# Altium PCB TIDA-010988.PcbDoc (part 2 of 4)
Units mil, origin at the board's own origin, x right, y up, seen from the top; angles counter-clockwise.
Board outline 3937.01 x 2559.06 mil, 4 copper layers (Top Layer, GND1, GND2, Bottom Layer), stack 61.6 mil thick; 270 components, 141 nets, 796 pads, 474 vias.
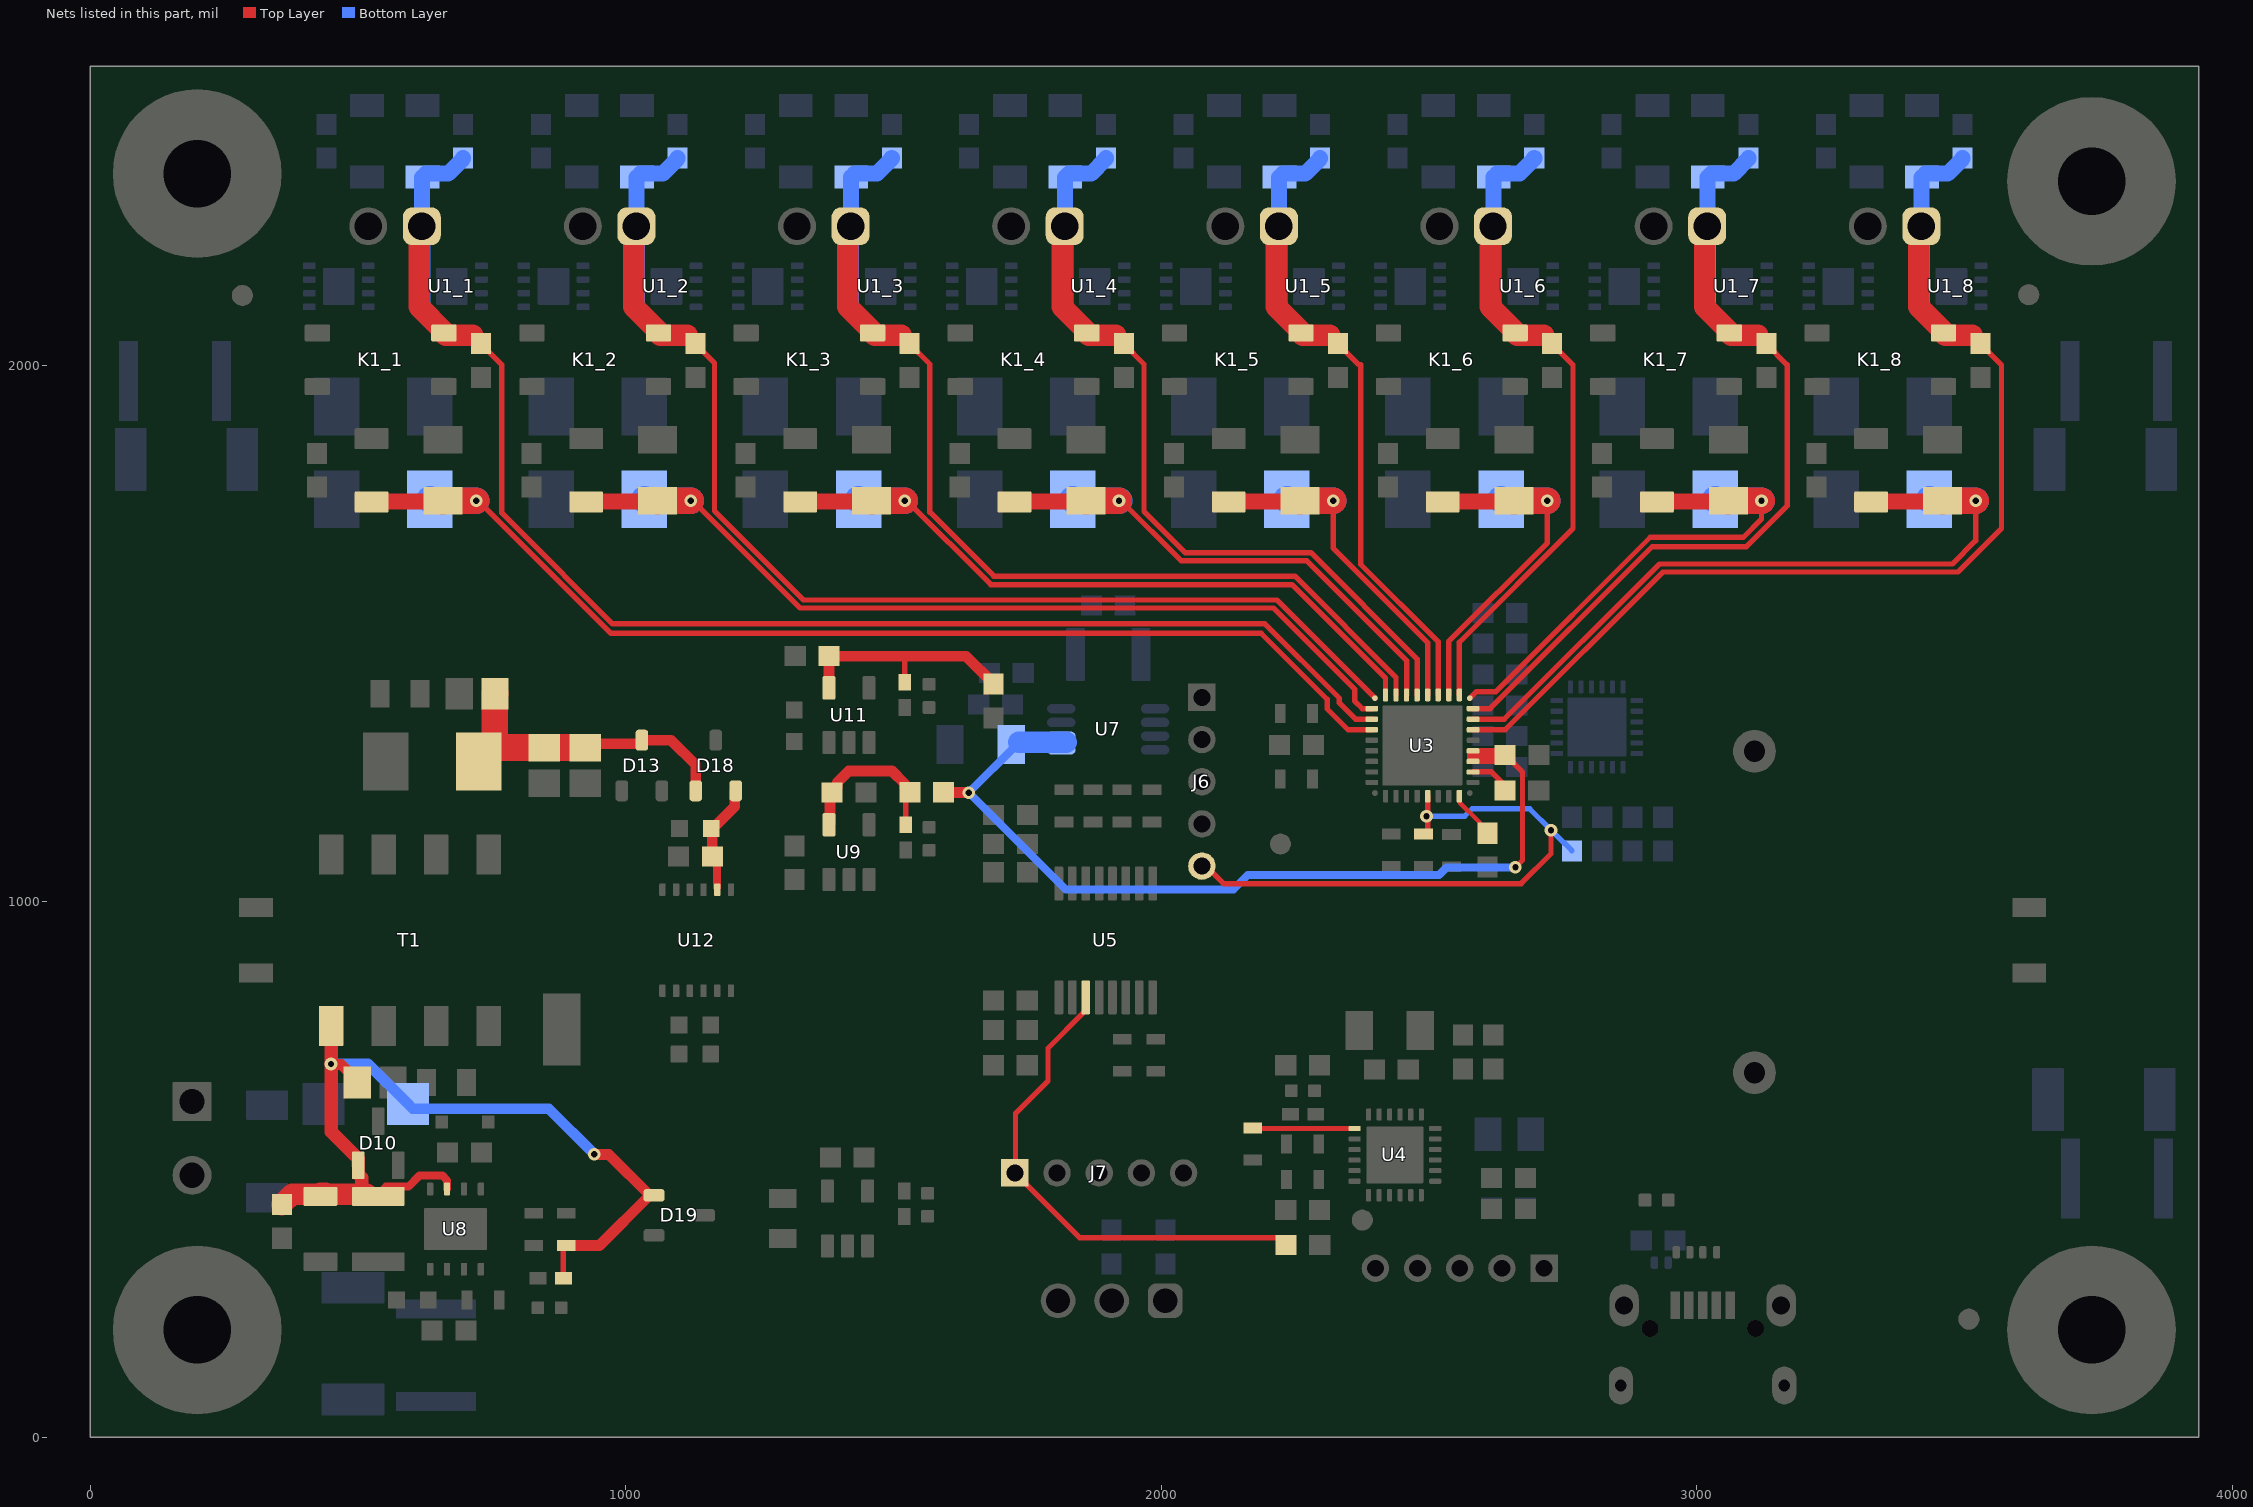
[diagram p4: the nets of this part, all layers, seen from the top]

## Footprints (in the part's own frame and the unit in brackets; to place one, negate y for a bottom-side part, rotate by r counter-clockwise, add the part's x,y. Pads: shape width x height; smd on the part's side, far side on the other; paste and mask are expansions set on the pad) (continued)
WCAP-CSGP_0603_L1.6W0.8H0.8_Reflow [mm] "Ceramic Capacitors, body 1.6x0.8mm"
  rect 0.8x0.8 smd: 1(-0.75,0) 2(0.75,0)
  body extent -0.8,-0.4 0.8,0.4, height 0.8
WCAP-CSGP_0805_L2W1.25H0.6_Reflow [mm] "Ceramic Capacitors, body 2x1.25mm"
  rect 0.9x1.3 smd: 1(-0.95,0) 2(0.95,0)
  body extent -1,-0.63 1,0.63, height 0.6
WCAP-CSGP_0805_L2W1.25H1.25 [mm] "Ceramic Capacitors, body 2x1.25mm"
  rect 0.9x1.3 smd: 1(-0.95,0) 2(0.95,0)
  body extent -1,-0.63 1,0.63, height 1.25
WCAP-CSMH_1206_L3.2W1.6H1.6 [mm] "Ceramic Capacitors, body 3.2x1.6mm"
  rect 0.9x1.6 smd: 1(-1.55,0) 2(1.55,0)
  silkscreen extent -0.75,-0.87 0.75,0.87, body extent -1.6,-0.8 1.6,0.8, height 1.6
WCAP-CSMH_1812_L4.5W3.2H2.5 [mm] "Ceramic Capacitors, body 4.5x3.2mm"
  rect 0.9x3.8 smd: 1(-2.2,0) 2(2.2,0)
  silkscreen extent -1.4,-1.75 1.4,1.75, body extent -2.25,-1.6 2.25,1.6, height 2.5
WEEE_Minimum [mil] "WEEElie bin"
  silkscreen extent -95,-172 99,104
WL-SMCC_0402_Green [mm] "SMD, 2-Leads, Body 1x0.5mm"
  rrect17% 0.6x0.6 smd: 1(-0.55,0) 2(0.55,0)
  body extent -0.5,-0.25 0.5,0.25, height 0.39
WURTH_61300311121 [mm] "Header, 2.54mm, 3x1, TH"
  rrect50% 1.65x1.65 hole 1.15: 1(-2.54,0)
  round 1.65 hole 1.15: 2(0,0) 3(2.54,0)
  body extent -3.81,-1.27 3.81,1.27, height 8.54
Wurth_691210910002 [mm] "Receptacle, 2.54mm, 2x1, R/A, TH"
  rrect50% 1.8x1.8 hole 1.3: 1(-1.27,0)
  round 1.8 hole 1.3: 2(1.27,0)
  silkscreen extent -3.2,-3.25 2.77,3.25, body extent -2.77,-3.25 2.77,3.25, height 8.85

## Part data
C1_1 C1_2 C1_3 C1_4 C1_5 C1_6 C1_7 C1_8 C2_1 C2_2 C2_3 C2_4 C2_5 C2_6 C2_7 C2_8: library part CMP-0084048-1, "CAP, CERM, 0.022 µF, 1000 V,+/- 10%, X7R, AEC-Q200 Grade 1, 1206", Cap_Case=1206, Manufacturer=Kemet, TempCo=X7R, Tolerance_%=10%, Value2=1000V, ValueDisplayed=0.022µF
C3 C4 C5 C6 C7 C8 C23: library part CMP-0006833-4, "CAP, CERM, 1 uF, 25 V, +/- 10%, X7R, 0603", Cap_Case=0603, Manufacturer="Wurth Elektronik", Supplier Part Number 1=732-7994-1-ND, TempCo=X7R, Tolerance_%=10%, Value1=Unknown, Value2=25V, ValueDisplayed=1uF
C9 C10 C11 C12 C13 C14 C16 C39: library part CMP-0006832-5, "CAP, CERM, 0.1 uF, 25 V, +/- 10%, X7R, 0603", Cap_Case=0603, Manufacturer="Wurth Elektronik", Supplier Part Number 1=710-885012206071, TempCo=X7R, Tolerance_%=10%, Value1=Unknown, Value2=25V, ValueDisplayed=0.1uF
C15: library part CMP-0006975-4, "CAP, CERM, 0.01 uF, 25 V, +/- 5%, C0G/NP0, 0603", Cap_Case=0603, Manufacturer=Kemet, Supplier Part Number 1=399-5779-1-ND, TempCo=C0G/NP0, Tolerance_%=5%, Value1=Unknown, Value2=25V, ValueDisplayed=0.01uF
C17 C22: library part CMP-0008574-2, "CAP, CERM, 10 uF, 25 V, +/- 10%, X7R, 1206", Cap_Case=1206, Manufacturer="Wurth Elektronik", Supplier Part Number 1=732-7574-1-ND, TempCo=X7R, Tolerance_%=10%, Value1=Unknown, Value2=25V, ValueDisplayed=10uF
C18: library part CMP-0119379-1, "WCAP-CSGP Multilayer Ceramic Chip Capacitor, General Purpose, size 0603, X7R, 470nF, 25VDC", Capacitance Tolerance=+/-10%, Case/Size Code=0603, Insulation Resistance=1.1GOhm, Manufacturer="Wurth Elektronik", Operating Temperature Max=125°C, Operating Temperature Min=-55°C, Rated Voltage (DC)=25V
C19: library part CMP-0007576-2, "CAP, CERM, 0.47 uF, 25 V, +/- 10%, X5R, 0805", Cap_Case=0805, Manufacturer=AVX, Supplier Part Number 1=478-1407-1-ND, TempCo=X5R, Tolerance_%=10%, Value1="0.017 ohm", Value2=25V, ValueDisplayed=0.47uF
C20 C30: library part CMP-0119825-1, "WCAP-CSMH Multilayer Ceramic Chip Capacitor, Mid and High Voltage, size 1206, X7R Class II, 1nF, 2000VDC", Capacitance Tolerance=10%, Case/Size Code=1206, Insulation Resistance=10GOhm, Manufacturer="Wurth Elektronik", Operating Temperature Max=125°C, Operating Temperature Min=-55°C, Rated Voltage (DC)=2000V
C21: library part CMP-0096740-1, "22 µF ±10% 25V Ceramic Capacitor X7R 1210 (3225 Metric)", Manufacturer=Wurth, Operating Temperature Range="-55°C to +125°C", TempCo=15%, Temperature Characteristic=X7R, Tolerance_%=10%, ValueDisplayed=22uF
C24 C25: library part CMP-0119848-1, "WCAP-CSMH Multilayer Ceramic Chip Capacitor, Mid and High Voltage, size 1812, X7R Class II, 2.2nF, 3000VDC", Capacitance Tolerance=10%, Case/Size Code=1812, Insulation Resistance=10GOhm, Manufacturer="Wurth Elektronik", Operating Temperature Max=125°C, Operating Temperature Min=-55°C, Rated Voltage (DC)=3000V
C26 C27: library part CMP-0118967-1, "WCAP-CSGP Multilayer Ceramic Chip Capacitor, General Purpose, size 0805, NP0, 22pF, 50VDC", Capacitance Tolerance=+/-5%, Case/Size Code=0805, Insulation Resistance=10GOhm, Manufacturer="Wurth Elektronik", Operating Temperature Max=125°C, Operating Temperature Min=-55°C, Rated Voltage (DC)=50V
C28 C29: library part CMP-0078699-1, "CAP, CERM, 47 µF, 10 V,+/- 20%, X5R, 0805", Cap_Case=0805, Manufacturer=MuRata, Supplier Part Number 1=490-9961-1-ND, TempCo=X5R, Tolerance_%=20%, Value2=10V, ValueDisplayed=47µF
C31: library part CMP-0088282-2, "4.7µF ±10% 50V Ceramic Capacitor X7R 1206 (3216 Metric)", Manufacturer="Wurth Electronics", TempCo=15%, Tolerance_%=10%, ValueDisplayed=4.7uF
C32: library part CMP-0096739-1, "4.7 µF ±10% 50V Ceramic Capacitor X7R 1210 (3225 Metric)", Digikey Part Number=732-7386-1-ND, Manufacturer=Wurth, Mouser Part Number=710-885012209048, Operating Temperature Range="-55°C to +125°C", TempCo=15%, Temperature Characteristic=X7R, Tolerance_%=10%, ValueDisplayed=4.7uF
C33: library part CMP-0006837-4, "CAP, CERM, 0.1 uF, 50 V, +/- 10%, X7R, 0603", Cap_Case=0603, Manufacturer="Wurth Elektronik", TempCo=X7R, Tolerance_%=10%, Value1=Unknown, Value2=50V, ValueDisplayed=0.1uF
C34: library part CMP-0119400-1, "WCAP-CSGP Multilayer Ceramic Chip Capacitor, General Purpose, size 0603, X7R, 47nF, 50VDC", Capacitance Tolerance=+/-10%, Case/Size Code=0603, Insulation Resistance=10GOhm, Manufacturer="Wurth Elektronik", Operating Temperature Max=125°C, Operating Temperature Min=-55°C, Rated Voltage (DC)=50V
C35 C36 C38 C40: library part CMP-0006831-4, "CAP, CERM, 1 uF, 16 V, +/- 10%, X7R, 0603", Cap_Case=0603, Manufacturer="Wurth Elektronik", Supplier Part Number 1=710-885012206052, TempCo=X7R, Tolerance_%=10%, Value1=Unknown, Value2=16V, ValueDisplayed=1uF
C37: library part CMP-0119543-1, "WCAP-CSGP Multilayer Ceramic Chip Capacitor, General Purpose, size 0805, X7R Class II, 470nF, 100VDC", Capacitance Tolerance=+/-10%, Case/Size Code=0805, Insulation Resistance=0.2GOhm, Manufacturer="Wurth Elektronik", Operating Temperature Max=125°C, Operating Temperature Min=-55°C, Rated Voltage (DC)=100V
C41 C43: library part CMP-0119369-1, "WCAP-CSGP Multilayer Ceramic Chip Capacitor, General Purpose, size 0603, X7R, 15nF, 25VDC", Capacitance Tolerance=+/-10%, Case/Size Code=0603, Insulation Resistance=10GOhm, Manufacturer="Wurth Elektronik", Operating Temperature Max=125°C, Operating Temperature Min=-55°C, Rated Voltage (DC)=25V
C42: library part CMP-0096736-1, "10 µF ±20% 25V Ceramic Capacitor X5R 0603 (1608 Metric)", Manufacturer=Wurth, Operating Temperature Range="-55°C to +85°C", TempCo=15%, Temperature Characteristic=X5R, Tolerance_%=20%, ValueDisplayed=10uF
C44: library part CMP-0081159-1, "CAP, CERM, 22 µF, 16 V,+/- 20%, X5R, 0603", Cap_Case=0603, Manufacturer=Samsung, Supplier Part Number 1=1276-7076-1-ND, TempCo=X5R, Tolerance_%=20%, Value2=16V, ValueDisplayed=22µF
C45 C46: library part CMP-0115919-1, "WCAP-CSMH Multilayer Ceramic Chip Capacitor, Mid and High Voltage, size 1812, X7R Class II, 2.2nF, 3000VDC", Capacitance Tolerance=10%, Case/Size Code=1812, Insulation Resistance=10GOhm, Manufacturer="Wurth Elektronik", Operating Temperature Max=125°C, Operating Temperature Min=-55°C, Rated Voltage (DC)=3000V
D1_1 D1_2 D1_3 D1_4 D1_5 D1_6 D1_7 D1_8 D2_1 D2_2 D2_3 D2_4 D2_5 D2_6 D2_7 D2_8: library part CMP-0005627-4, "Diode, Zener, 11 V, 550 mW, SMB", Manufacturer="ON Semiconductor", Power_W=550mW, Value1=0.55W
D3 D7 D15 D17 D20 D21: library part CMP-0081765-2, "LED, Green, SMD", Color=Green, Manufacturer="Wurth Elektronik", Power_TotalModule=99mW, Value1=0.099W, Value2=3.2V
D4 D5 D6: library part CMP-0074647-4, "1-Channel ESD Protection Diode with Low RDYN and Low Clamping Voltage, DPY0002A (X1SON-2)", Alternate Manufacturer="Texas Instruments", Alternate PartNumber=ESD401DPYT, Operating Temperature Range="-40 to 125 C", Rating=Catalog
D10: library part CMP-0126396-1, "Zener Diode 27 V 250 mW ±5% Surface Mount SOT-23-3", Digikey Part Number=296-BZX84C27VDBZRQ1CT-ND, Manufacturer="Texas Instruments", Max Reverse Leakage Current=0.03uA, Mouser Part Number=595-BZX84C27VDBZRQ1, Operating Temperature Range="-55°C to +150°C", Power_W=250mW
D11: library part CMP-0028909-2, "Diode, Schottky, 30 V, 2 A, AEC-Q101, SMB", Manufacturer=Vishay-Semiconductor, Value1=2A, Value2=0.47V
D12: library part CMP-0029019-2, "Diode, Ultrafast, 75 V, 0.25 A, SOD-323", Manufacturer="Central Semiconductor", Value1=0.25A, Value2=1.2V
D13: library part CMP-0005972-3, "Diode, Zener, 8.2 V, 225 mW, SOT-23", Manufacturer="ON Semiconductor", Power_W=225mW, Value1=0.225W
D14: library part CMP-0028353-2, "Diode, Schottky, 40 V, 3 A, SMA", Manufacturer="Diodes Inc.", Value1=3A, Value2=0.5V
D16: library part CMP-0088101-2, "DIODE SCHOTTKY 20V 1A PMDTM", Manufacturer=Rohm
D18 D19: library part CMP-0028570-2, "Diode, Schottky, 20 V, 0.4 A, SOT-23", Manufacturer="Diodes Inc.", Value1=0.4A, Value2=0.35V
F1_1 F1_2 F1_3 F1_4 F1_5 F1_6 F1_7 F1_8: library part CMP-0125283-2, "Polymeric PTC Resettable Fuse 30V 200 mA Ih Surface Mount 1206 (3216 Metric), Concave", Digikey Part Number=18-NANOASMDCH020F-2CT-ND, Hold Current=0.2A, Manufacturer=Littelfuse, Mouser Part Number=576-NANOASMDCH020F-2, Operating Temperature Range="-40°C to +125°C", Trip Current=0.6A
FID1 FID2 FID3 FID4 FID5 FID6: library part CMP-0077181-1, "Fiducial mark.  There is nothing to buy or mount.", Manufacturer=N/A
H1 H2 H3 H4: library part CMP-0003617-1, "Machine Screw, Round, #4-40 x 1/4, Nylon, Philips panhead", Manufacturer="B&F Fastener Supply", Supplier Part Number 1=H542-ND
H5 H6 H7 H8: library part CMP-0003610-1, "Standoff, Hex, 0.5\"L #4-40 Nylon", Manufacturer=Keystone, Supplier Part Number 1=36-1902C-ND
J1_1 J1_2 J1_3 J1_4 J1_5 J1_6 J1_7 J1_8: library part CMP-0054769-2, "Receptacle, 2.54mm, 2x1, Tin, R/A, TH", Color=Green, Current_A=6A, Manufacturer="Wurth Elektronik", Voltage_V=150V
J2: library part CMP-0086695-3, "USB - micro B USB 2.0 Receptacle Connector 5 Position Surface Mount, Right Angle; Through Hole", Current_A=3A, Manufacturer="Wurth Electronics", Voltage_V=30V
J3: library part CMP-0054796-4, "Header, 2.54 mm, 3x1, Gold, TH", Manufacturer="Wurth Elektronik", Supplier Part Number 1=732-5316-ND
J4 J6 J7: library part CMP-0075212-1, "Header, 2mm, 5x1, Gold, TH", Color=Black, Current_A=1A, Manufacturer=Harwin, Supplier Part Number 1=952-1314-ND, Voltage_V=500V
J5: library part CMP-0095471-2, "2 Position Wire to Board Terminal Block Horizontal with Board 0.138\" (3.50mm) Through Hole", Current_A=10A, Digikey Part Number=732-2745-ND, Manufacturer=Wurth, Mouser Part Number=710-691103110002, Operating Temperature Range="-40°C to +105°C", Voltage_V=125V
K1_1 K1_2 K1_3 K1_4 K1_5 K1_6 K1_7 K1_8: library part CMP-0125248-1, "Relay SSR 1mA 1.75V DC-IN 2A 60V AC/DC-OUT 4-Pin SOP Tube", Digikey Part Number=255-AQY232G3HS-ND, Input Current=20mA, Manufacturer=Panasonic, Max Power Dissipation=530mW, Mouser Part Number=769-AQY232G3HS, On State Resistance=0.07Ω, Operating Temperature Range="-40°C to +125°C", Output Voltage=48V, ValueDisplayed=0.8pF, Voltage_Isolation_Vrms=3750Vrms
L1 L2 L3 L4 L5: library part CMP-0003285-2, "Ferrite Bead, 600 ohm @ 100 MHz, 1 A, 0603", Manufacturer="Wurth Elektronik", Supplier Part Number 1=732-6703-1-ND, Value1="0.2 ohm", Value2=1A, ValueDisplayed="600 ohm"
LBL1: library part CMP-0003625-1, "Thermal Transfer Printable Labels, 0.650\" W x 0.200\" H - 10,000 per roll", Manufacturer=Brady, Supplier Part Number 1=97C5133
Logo1: library part CMP-0074844-2, Manufacturer="Texas Instruments"
Logo2: library part CMP-0074838-1, "Texas Instrument Corporate Signature"
Logo3: library part CMP-0074847-1, "FCC_disclaimer"
Logo4: library part CMP-0074769-4, Manufacturer="Texas Instruments"
R0_1 R0_2 R0_3 R0_4 R0_5 R0_6 R0_7 R0_8 R6 R15 R23 R26: library part CMP-0025697-4, "RES, 0, 5%, 0.1 W, AEC-Q200 Grade 0, 0603", Manufacturer=Vishay-Dale, Power_W=100mW, Supplier Part Number 1=541-0.0GCT-ND, TempCo="200 ppm/C", Tolerance_%=5%, Value2=0.1W, Value_Code=0000, ValueDisplayed=0
R1_1 R1_2 R1_3 R1_4 R1_5 R1_6 R1_7 R1_8 R2_1 R2_2 R2_3 R2_4 R2_5 R2_6 R2_7 R2_8: library part CMP-0023358-4, "RES, 10 M, 0.5%, 0.1 W, AEC-Q200 Grade 0, 0603", Manufacturer=Vishay-Dale, Power_W=100mW, Supplier Part Number 1=541-10MAYCT-ND, TempCo="50 ppm/C", Tolerance_%=0.5%, Value2=0.1W, Value_Code=10M0, ValueDisplayed=10M
R3_1 R3_2 R3_3 R3_4 R3_5 R3_6 R3_7 R3_8: library part CMP-0024131-2, "RES, 340, 0.1%, 0.1 W, 0603", Manufacturer="Yageo America", Power_W=100mW, TempCo="25 ppm/C", Tolerance_%=0.1%, Value2=0.1W, Value_Code=340R, ValueDisplayed=340
R4_1 R4_2 R4_3 R4_4 R4_5 R4_6 R4_7 R4_8: library part CMP-0018822-2, "RES, 249, 0.1%, 0.25 W, 1206", Manufacturer=Vishay-Dale, Power_W=250mW, Supplier Part Number 1=TNP249ACCT-ND, TempCo="25 ppm/C", Tolerance_%=0.1%, Value2=0.25W, Value_Code=249R, ValueDisplayed=249
R5 R9 R12 R17 R18 R19 R20 R21 R22 R29 R30: library part CMP-0025334-3, "RES, 49.9, 0.5%, 0.1 W, 0603", Manufacturer="Yageo America", Power_W=100mW, TempCo="50 ppm/C", Tolerance_%=0.5%, Value2=0.1W, Value_Code=49R9, ValueDisplayed=49.9
R7: library part CMP-0025862-4, "RES, 8.2 k, 5%, 0.1 W, AEC-Q200 Grade 0, 0603", Manufacturer=Vishay-Dale, Power_W=100mW, Supplier Part Number 1=541-8.2KGCT-ND, TempCo="200 ppm/C", Tolerance_%=5%, Value2=0.1W, Value_Code=8k20, ValueDisplayed=8.2k
R8: library part CMP-0023032-4, "RES, 330 k, 1%, 0.1 W, 0603", Manufacturer=Yageo, Power_W=100mW, Supplier Part Number 1=311-330KHRCT-ND, TempCo="100 ppm/C", Tolerance_%=1%, Value2=0.1W, Value_Code=330k
R10 R56: library part CMP-0021998-4, "RES, 10.0 k, 1%, 0.1 W, AEC-Q200 Grade 0, 0603", Manufacturer=Vishay-Dale, Power_W=100mW, Supplier Part Number 1=541-10.0KHCT-ND, TempCo="100 ppm/C", Tolerance_%=1%, Value2=0.1W, Value_Code=10k0, ValueDisplayed=10.0k
R11: library part CMP-0022917-4, "RES, 220 k, 1%, 0.1 W, 0603", Manufacturer=Yageo, Power_W=100mW, Supplier Part Number 1=311-220KHRCT-ND, TempCo="100 ppm/C", Tolerance_%=1%, Value2=0.1W, Value_Code=220k
R13 R14 R27 R28 R31 R32: library part CMP-0023153-5, "RES, 4.70 k, 1%, 0.1 W, 0603", Manufacturer=Yageo, Power_W=100mW, Supplier Part Number 1=311-4.70KHRCT-ND, TempCo="100 ppm/C", Tolerance_%=1%, Value2=0.1W, Value_Code=4k70, ValueDisplayed=4.70k
R16 R25: library part CMP-0025925-5, "RES, 47 k, 5%, 0.1 W, 0603", Manufacturer=Yageo, Power_W=100mW, Supplier Part Number 1=311-47KGRCT-ND, TempCo="100 ppm/C", Tolerance_%=5%, Value2=0.1W, Value_Code=47k0, ValueDisplayed=47k
R24: library part CMP-0023363-3, "RES, 100 k, 0.1%, 0.1 W, AEC-Q200 Grade 0, 0603", Manufacturer=Panasonic, Power_W=100mW, Supplier Part Number 1=P100KDBCT-ND, TempCo="25 ppm/C", Tolerance_%=0.1%, Value2=0.1W, Value_Code=100k
R33: library part CMP-0023427-3, "RES, 120 k, 0.1%, 0.1 W, 0603", Manufacturer="Susumu Co Ltd", Power_W=100mW, Supplier Part Number 1=RG16P120KBCT-ND, TempCo="25 ppm/C", Tolerance_%=0.1%, Value2=0.1W, Value_Code=120k
R34 R54 R55: library part CMP-0026918-5, "RES, 3.3 k, 5%, 0.063 W, AEC-Q200 Grade 0, 0402", Manufacturer=Vishay-Dale, Power_W=63mW, Supplier Part Number 1=541-3.3KJCT-ND, TempCo="200 ppm/C", Tolerance_%=5%, Value2=0.063W, Value_Code=3k30, ValueDisplayed=3.3k
R35: library part CMP-0022726-3, "RES, 0.047, 1%, 0.1 W, AEC-Q200 Grade 1, 0603", Manufacturer=Panasonic, Power_W=100mW, Supplier Part Number 1=P47LJCT-ND, TempCo="200 ppm/C", Tolerance_%=1%, Value2=0.1W, Value_Code=R047, ValueDisplayed=0.047
R36 R37 R39 R40: library part CMP-0089022-1, "RES SMD 3.3M OHM 1% 1/2W 2010", Manufacturer=Bourns, Power_W=500mW, TempCo=100ppm/°C, Tolerance_%=1%
R41: library part CMP-0026982-5, "RES, 8.2 k, 5%, 0.063 W, AEC-Q200 Grade 0, 0402", Manufacturer=Vishay-Dale, Power_W=63mW, Supplier Part Number 1=541-8.2KJCT-ND, TempCo="200 ppm/C", Tolerance_%=5%, Value2=0.063W, Value_Code=8k20, ValueDisplayed=8.2k
R42 R43: library part CMP-0018851-2, "RES, 100, 0.1%, 0.125 W, 0805", Manufacturer="Susumu Co Ltd", Power_W=125mW, Supplier Part Number 1=RG20P100BCT-ND, TempCo="25 ppm/C", Tolerance_%=0.1%, Value2=0.125W, Value_Code=100R, ValueDisplayed=100
R46: library part CMP-0026963-3, "RES, 68 k, 5%, 0.063 W, AEC-Q200 Grade 0, 0402", Manufacturer=Vishay-Dale, Power_W=63mW, Supplier Part Number 1=541-68KJCT-ND, TempCo="200 ppm/C", Tolerance_%=5%, Value2=0.063W, Value_Code=68k0, ValueDisplayed=68k
R47: library part CMP-0023174-4, "RES, 536 k, 1%, 0.1 W, 0603", Manufacturer=Yageo, Power_W=100mW, Supplier Part Number 1=311-536KHRCT-ND, TempCo="100 ppm/C", Tolerance_%=1%, Value2=0.1W, Value_Code=536k
R48: library part CMP-0022836-4, "RES, 174 k, 1%, 0.1 W, 0603", Manufacturer=Yageo, Power_W=100mW, Supplier Part Number 1=311-174KHRCT-ND, TempCo="100 ppm/C", Tolerance_%=1%, Value2=0.1W, Value_Code=174k
R50: library part CMP-0022735-5, "RES, 100 k, 1%, 0.1 W, 0603", Manufacturer=Yageo, Power_W=100mW, Supplier Part Number 1=311-100KHRCT-ND, TempCo="100 ppm/C", Tolerance_%=1%, Value2=0.1W, Value_Code=100k
R51: library part CMP-0022784-4, "RES, 130 k, 1%, 0.1 W, 0603", Manufacturer=Yageo, Power_W=100mW, Supplier Part Number 1=311-130KHRCT-ND, TempCo="100 ppm/C", Tolerance_%=1%, Value2=0.1W, Value_Code=130k
R52: library part CMP-0022776-5, "RES, 12.1 k, 1%, 0.1 W, 0603", Manufacturer=Yageo, Power_W=100mW, Supplier Part Number 1=311-12.1KHRCT-ND, TempCo="100 ppm/C", Tolerance_%=1%, Value2=0.1W, Value_Code=12k1, ValueDisplayed=12.1k
T1: library part CMP-0096072-1, "Transformer, 0.13Ohm PRI, 0.019Ohm SEC, 3:1, 9.5x9.78x10.54mm SMT", Frequency_Fixed=350kHz, Manufacturer="Wurth Electronics", Operating Temperature Range="-40°C to +125°C"
TP1 TP2: library part CMP-0055138-2, "Test Point, Miniature, Black, TH", Color=Black, Manufacturer="Keystone Electronics", PartNumber=5001, Supplier Part Number 1=36-5001-ND
TP3 TP4: library part CMP-0003825-1, "1mm Test Point, SMT", Manufacturer=Any, PartNumber=TP_SM_1MM
TP5: library part CMP-0055152-2, "Test Point, Miniature, SMT", Manufacturer="Keystone Electronics", PartNumber=5015, Supplier Part Number 1=36-5015TR-ND
U1_1 U1_2 U1_3 U1_4 U1_5 U1_6 U1_7 U1_8 U2_1 U2_2 U2_3 U2_4 U2_5 U2_6 U2_7 U2_8: library part CMP-0081715-3, "33 V Bidirectional Flat-Clamp Surge Protection Device, DRB0008A (VSON-8)", Alternate Manufacturer="Texas Instruments", Alternate PartNumber=TVS3301DRBT, Operating Temperature Range="-40 to 125 C", Rating=Catalog
U3: library part CMP-0120762-1, Manufacturer="Texas Instruments", Operating Temperature Range=to
U4: library part CMP-0093957-1, "Mixed-Signal Microcontroller, VQFN24", Frequency_Fixed=80MHz, Manufacturer="Texas Instruments", Max Supply Voltage=3.6V, Min Supply Voltage=1.62V, Operating Temperature Range="-40°C to +125°C"
U5: library part CMP-0127533-1, "General-Purpose, Basic and Reinforced, Quad-Channel Digital Isolators", Alternate Manufacturer="Texas Instruments", Alternate PartNumber=ISO7741DBQ, PartNumber=ISO7741DBQR
U6: library part CMP-0122830-1, Manufacturer="Texas Instruments", Operating Temperature Range=to
U7: library part CMP-0076433-2, "5ppm/C High-Precision Voltage Reference with Integrated High-Bandwidth Buffer, DGK0008A (VSSOP-8)", Alternate Manufacturer="Texas Instruments", Alternate PartNumber=REF6025IDGKT
U8: library part CMP-0084791-1, "70-VIN PSR Flyback DC/DC Converter With 100-V, 1.5-A Integrated Power MOSFET, NGU0008C (WSON-8)", Alternate Manufacturer="Texas Instruments", Alternate PartNumber=LM5180NGUT
U9: library part CMP-0091339-1, "300-mA, ultra-low-noise, low-IQ, low-dropout (LDO) linear regulator with high PSRR 5-SOT-23 -40 to 125", Dropout Voltage=140mV, Manufacturer="Texas Instruments", Max Supply Voltage=6V, Min Supply Voltage=1.6V, Mouser Part Number=595-TPS7A2050PDBVR, Nominal Supply Current=6.5uA, Operating Temperature Range="-40°C to +125°C", Output Voltage=5V
U10 U11: library part CMP-0034271-1, "150-mA 30-V low-dropout (LDO) linear regulator with 3.2-μA supply current 5-SOT-23 -40 to 125", Digikey Part Number=296-TLV709A33DBVRCT-ND, Dropout Voltage=1000mV, Manufacturer="Texas Instruments", Max Supply Voltage=30V, Min Supply Voltage=4.3V, Mouser Part Number=595-TLV709A33DBVR, Nominal Supply Current=3.2uA, Operating Temperature Range="-40°C to +125°C", Output Voltage=3.3V
U12: library part CMP-0098322-4, "1.5W, High-Density, >3 kVRMS Isolated DC-DC Converter", Manufacturer="Texas Instruments", Max Supply Voltage=5.5V, Min Supply Voltage=4.5V, Operating Temperature Range=to, Output Voltage=5V
ZZ1: library part CMP-0003616-3
ZZ2: library part CMP-0077236-1
ZZ3: library part CMP-0077237-1
ZZ4: library part CMP-0077238-1

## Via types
v1: diameter 23.62, hole 11.81, Top Layer to Bottom Layer, tented both sides, 374 vias
v2: diameter 19.68, hole 7.87, Top Layer to Bottom Layer, tented top, 64 vias
v3: diameter 19.68, hole 7.87, Top Layer to Bottom Layer, tented both sides, 26 vias
v4: diameter 19.68, hole 7.87, Top Layer to Bottom Layer, 9 vias
v5: diameter 28, hole 12, Top Layer to Bottom Layer, tented both sides, 1 vias

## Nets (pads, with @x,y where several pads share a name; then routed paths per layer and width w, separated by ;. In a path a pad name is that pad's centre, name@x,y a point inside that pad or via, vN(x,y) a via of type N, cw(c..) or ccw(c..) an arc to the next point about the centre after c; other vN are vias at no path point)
3V3_ISO: C40.1 L4.2 R55.1 U11.5 | length 437.1
  Top Layer w10: R55.1@1521.22,1409.37 1521.22,1457.9 1521.31,1457.99
  Top Layer w20: U11.5@1379.61,1398.91 C40.1@1379.61,1457.99 1521.31,1457.99 1635.46,1457.99 L4.2@1686.73,1406.72
  Top Layer w30: L4.2@1686.73,1405.73 L4.2@1686.73,1406.72
5V5_ISO_OUT: C28.1 C29.1 D11.1 D13.3 D18.1 R42.2 | length 549.3
  Top Layer w20: C29.1@924.62,1287.27 931.51,1294.16 1028.4,1294.16 1030.21,1295.97 D13.3@1030.21,1301.05 1084.81,1301.05 1130.76,1255.1 1130.76,1214.44 D18.1@1130.76,1206.56
  Top Layer w50: D11.1@743.2,1287.27 C28.1@848.15,1287.27 C29.1@924.62,1287.27 ; D11.1@755.47,1302.6 755.47,1387.2 R42.2@756.06,1387.79
5V5_ISO_USB: C43.2 C44.1 D18.2 U12.8 | length 202.7
  Top Layer w15: C44.1@1161.75,1083.52 1170.95,1074.33 U12.8@1170.95,1026.35
  Top Layer w20: C44.1@1161.75,1083.52 1161.75,1136.23 1162.74,1136.23 1203.75,1177.24 1203.75,1204.75 D18.2@1205.56,1206.56
5V_ISO: C36.1 L5.2 R41.2 U9.5 | length 313.7
  Top Layer w10: R41.2@1522.71,1143.12 L5.2@1522.71,1203.81
  Top Layer w20: U9.5@1379.61,1143.12 1381.42,1144.93 1381.42,1197.47 C36.1@1380.3,1198.59 ; C36.1@1385.51,1203.81 1386.5,1203.81 1395.2,1212.51 1395.2,1222.2 1416.56,1243.56 1497.12,1243.56 1521.01,1219.67 1521.01,1212.57 1529.71,1203.87 L5.2@1530.69,1203.87
  Top Layer w25: C36.1@1380.3,1198.59 C36.1@1385.51,1203.81
  Top Layer w30: L5.2@1529.71,1203.87 L5.2@1530.69,1203.87
24V: C31.2 C32.2 C33.1 D10.1 D14.1 D19.1 R43.2 R46.2 R47.2 T1.4 U8.3 | length 1714.7
  Top Layer w10: R46.2@883.65,296.66 R47.2@883.65,352.56
  Top Layer w15: C32.2@538.17,453.23 552.33,467.38 594.54,467.38 615.32,488.17 657.74,488.17 666.53,479.38 U8.3@666.53,463.07
  Top Layer w20: v1@450.65,695.7 468.73,695.7 498.64,665.79 R43.2@498.64,661.85 ; R47.2@889.24,357.56 951.25,357.56 D19.1@1044.96,451.26 ; v1(941.33,528.25) 942.03,527.56 968.65,527.56 D19.1@1044.96,451.26 ; D19.1@1052.83,451.26 D19.1@1044.96,451.26 ; D19.1@1052.83,452.26 D19.1@1054.34,452.26
  Top Layer w25: v1@450.19,696.16 450.19,569.8 500.38,519.61 D10.1@500.38,507.21 501.07,506.52 501.07,490.32 507.36,484.03 507.36,462.38 516.52,453.23 C32.2@538.17,453.23 ; v1@450.19,696.39 T1.4@450.19,767.51
  Top Layer w40: C33.1@358,434.06 377.47,453.54 428.43,453.54 430.09,455.19 439.93,455.19 441.9,453.23 C32.2@516.52,453.23
  Bottom Layer w20: v1(449.96,696.39) 519.1,696.39 D14.1@593.45,622.04 602.48,613.02 856.57,613.02 v1(941.33,528.25)
A0: C1_6.1 J1_6.1 K1_6.4 R0_6.2 R1_6.2 U1_6.1 U1_6.2 U1_6.3 U1_6.4 U3.1 | length 1387.9
  Top Layer w10: U3.1@2556.54,1385.52 2556.54,1483.98 2768.8,1696.25 2768.8,2001.74 2729.93,2040.61 R0_6.2@2729.93,2041.59
  Top Layer w20: R0_6.2@2714.39,2057.14 R0_6.2@2729.93,2041.59
  Top Layer w40: J1_6.1@2619.48,2260.7 2614.52,2255.75 2614.52,2110.14 K1_6.4@2661.98,2062.68 ; K1_6.4@2660.69,2061.39 2660.69,2060.76 2664.31,2057.14 R0_6.2@2714.39,2057.14
  Bottom Layer w30: U1_6.1@2620.56,2114.16 2620.56,2259.62 J1_6.1@2619.48,2260.7 2620.07,2261.3 2620.07,2351.89 C1_6.1@2620.66,2352.48 2627.31,2359.13 2668.63,2359.13 2696.43,2386.93 R1_6.2@2696.43,2387.91
A1: D2_6.2 F1_6.2 R4_6.1 U3.2 | length 722.5
  Top Layer w10: U3.2@2536.73,1385.4 2536.73,1485.39 2720.85,1669.5 v1(2720.85,1748)
  Top Layer w30: F1_6.2@2525.67,1745.96 2526.66,1746.95 2657.88,1746.95 R4_6.1@2658.86,1747.93
  Top Layer w50: R4_6.1@2658.86,1747.93 2658.93,1748 v1(2720.85,1748)
  Bottom Layer w50: D2_6.2@2634.5,1751.05 2637.57,1748 v1(2720.85,1748)
A2: C1_5.1 J1_5.1 K1_5.4 R0_5.2 R1_5.2 U1_5.1 U1_5.2 U1_5.3 U1_5.4 U3.3 | length 1359.7
  Top Layer w10: R0_5.2@2330.07,2041.59 2330.07,2040.61 2368.22,2002.46 ; 2372.42,2002.46 2372.42,1629.62 2517.05,1485 U3.3@2517.05,1385.4
  Top Layer w20: R0_5.2@2314.53,2057.14 R0_5.2@2330.07,2041.59
  Top Layer w40: J1_5.1@2219.61,2260.7 2214.65,2255.75 2214.65,2110.14 K1_5.4@2262.11,2062.68 ; K1_5.4@2260.83,2061.39 2260.83,2060.76 2264.45,2057.14 R0_5.2@2314.53,2057.14
  Bottom Layer w30: U1_5.1@2220.7,2114.16 2220.7,2139.75 2220.7,2165.34 2220.7,2190.93 2220.7,2259.62 J1_5.1@2219.61,2260.7 2220.2,2261.3 2220.2,2351.89 C1_5.1@2220.8,2352.48 2227.45,2359.13 2268.77,2359.13 2296.57,2386.93 R1_5.2@2296.57,2387.91
A3: D2_5.2 F1_5.2 R4_5.1 U3.4 | length 719.2
  Top Layer w10: v1(2320.99,1748) 2320.99,1659.85 2497.48,1483.35 U3.4@2497.48,1385.52
  Top Layer w30: F1_5.2@2125.81,1745.96 2126.8,1746.95 2258.02,1746.95 R4_5.1@2259,1747.93
  Top Layer w50: R4_5.1@2259,1747.93 2259.07,1748 v1(2320.99,1748)
  Bottom Layer w50: D2_5.2@2234.64,1751.05 2237.71,1748 v1(2320.99,1748)
A4: C1_4.1 J1_4.1 K1_4.4 R0_4.2 R1_4.2 U1_4.1 U1_4.2 U1_4.3 U1_4.4 U3.5 | length 1648.2
  Top Layer w10: R0_4.2@1930.21,2041.59 1930.21,2040.61 1967.85,2002.97 1967.85,1728.03 2044.56,1651.32 2279.26,1651.32 2477.8,1452.79 U3.5@2477.8,1385.52
  Top Layer w20: R0_4.2@1914.67,2057.14 R0_4.2@1930.21,2041.59
  Top Layer w40: J1_4.1@1819.75,2260.7 1814.79,2255.75 1814.79,2110.14 K1_4.4@1862.25,2062.68 ; K1_4.4@1860.96,2061.39 1860.96,2060.76 1864.59,2057.14 R0_4.2@1914.67,2057.14
  Bottom Layer w30: U1_4.1@1820.84,2114.16 1820.84,2259.62 J1_4.1@1819.75,2260.7 1820.34,2261.3 1820.34,2351.89 C1_4.1@1820.93,2352.48 1827.59,2359.13 1868.91,2359.13 1896.71,2386.93 R1_4.2@1896.71,2387.91
A5: D2_4.2 F1_4.2 R4_4.1 U3.6 | length 1003.8
  Top Layer w10: v1@1925.32,1748 2037,1636.32 2271.53,1636.32 2458.11,1449.75 U3.6@2458.11,1385.52
  Top Layer w30: F1_4.2@1725.95,1745.96 1726.93,1746.95 1858.15,1746.95 R4_4.1@1859.14,1747.93
  Top Layer w50: R4_4.1@1859.14,1747.93 1859.21,1748 v1@1920.75,1748
  Bottom Layer w50: D2_4.2@1834.78,1751.05 1837.85,1748 v1(1921.12,1748)
A6: C1_3.1 J1_3.1 K1_3.4 R0_3.2 R1_3.2 U1_3.1 U1_3.2 U1_3.3 U1_3.4 U3.7 | length 1989.4
  Top Layer w10: R0_3.2@1530.35,2040.61 1567.91,2003.05 1567.91,1726.77 1687.42,1607.25 2249.67,1607.25 2438.43,1418.5 U3.7@2438.43,1385.52
  Top Layer w20: R0_3.2@1514.81,2057.14 R0_3.2@1530.35,2041.59 R0_3.2@1530.35,2040.61
  Top Layer w40: J1_3.1@1419.89,2260.7 1414.93,2255.75 1414.93,2110.14 K1_3.4@1462.39,2062.68 ; K1_3.4@1461.1,2061.39 1461.1,2060.76 1464.72,2057.14 R0_3.2@1514.81,2057.14
  Bottom Layer w30: U1_3.1@1420.98,2114.16 1420.98,2259.62 J1_3.1@1419.89,2260.7 1420.48,2261.3 1420.48,2351.89 C1_3.1@1421.07,2352.48 1427.73,2359.13 1469.05,2359.13 1496.85,2386.93 R1_3.2@1496.85,2387.91
A7: D2_3.2 F1_3.2 R4_3.1 U3.8 | length 1345.5
  Top Layer w10: v1@1525.46,1748 1681.89,1591.56 2244.14,1591.56 2418.74,1416.97 U3.8@2418.74,1385.52
  Top Layer w30: F1_3.2@1326.09,1745.96 1327.07,1746.95 1458.29,1746.95 R4_3.1@1459.28,1747.93
  Top Layer w50: R4_3.1@1459.28,1747.93 1459.34,1748 v1(1521.26,1748)
  Bottom Layer w50: D2_3.2@1434.92,1751.05 1437.99,1748 v1(1521.26,1748)
A8: C1_2.1 J1_2.1 K1_2.4 R0_2.2 R1_2.2 U1_2.1 U1_2.2 U1_2.3 U1_2.4 U3.9 | length 2333
  Top Layer w10: R0_2.2@1130.49,2041.59 1130.49,2040.61 1165.77,2005.32 1165.77,1729.04 1331.9,1562.91 2215.76,1562.91 U3.9@2399.06,1379.61
  Top Layer w20: R0_2.2@1114.94,2057.14 R0_2.2@1130.49,2041.59
  Top Layer w40: J1_2.1@1020.03,2260.7 1015.07,2255.75 1015.07,2110.14 K1_2.4@1062.53,2062.68 ; K1_2.4@1061.24,2061.39 1061.24,2060.76 1064.86,2057.14 R0_2.2@1114.94,2057.14
  Bottom Layer w30: U1_2.1@1021.11,2114.16 1021.11,2259.62 J1_2.1@1020.03,2260.7 1020.62,2261.3 1020.62,2351.89 C1_2.1@1021.21,2352.48 1027.86,2359.13 1069.19,2359.13 1096.98,2386.93 R1_2.2@1096.98,2387.91
A9: D2_2.2 F1_2.2 R4_2.1 U3.10 | length 1724.8
  Top Layer w10: v1@1125.6,1748 1325.69,1547.91 2209.55,1547.91 2361.15,1396.31 2361.15,1374.21 2375.36,1360.01 2393.07,1360.01 U3.10@2393.15,1359.93
  Top Layer w30: F1_2.2@926.23,1745.96 927.21,1746.95 1058.43,1746.95 R4_2.1@1059.42,1747.93
  Top Layer w50: R4_2.1@1059.42,1747.93 1059.48,1748 v1(1121.4,1748)
  Bottom Layer w50: D2_2.2@1035.06,1751.05 1038.12,1748 v1(1121.4,1748)
A10: C1_1.1 J1_1.1 K1_1.4 R0_1.2 R1_1.2 U1_1.1 U1_1.2 U1_1.3 U1_1.4 U3.11 | length 2749.1
  Top Layer w10: R0_1.2@729.87,2041.59 729.87,2040.61 768.74,2001.74 768.74,1725.45 793.54,1700.65 975.81,1518.38 2193.45,1518.38 2332.43,1379.4 2332.43,1370.7 2362.89,1340.24 U3.11@2393.15,1340.24
  Top Layer w20: R0_1.2@714.33,2057.14 R0_1.2@729.87,2041.59
  Top Layer w40: J1_1.1@619.41,2260.7 614.45,2255.75 614.45,2110.14 K1_1.4@661.91,2062.68 ; K1_1.4@660.62,2061.39 660.62,2060.76 664.24,2057.14 R0_1.2@714.33,2057.14
  Bottom Layer w30: U1_1.1@620.5,2114.16 620.5,2259.62 J1_1.1@619.41,2260.7 620,2261.3 620,2351.89 C1_1.1@620.59,2352.48 627.25,2359.13 668.57,2359.13 696.37,2386.93 R1_1.2@696.37,2387.91
A11: D2_1.2 F1_1.2 R4_1.1 U3.12 | length 2139.2
  Top Layer w10: v1@724.98,1748 972.3,1500.68 2186.67,1500.68 2309.9,1377.45 2309.9,1359.69 2349.04,1320.56 U3.12@2393.15,1320.56
  Top Layer w30: F1_1.2@525.61,1745.96 526.59,1746.95 657.81,1746.95 R4_1.1@658.8,1747.93
  Top Layer w50: R4_1.1@658.8,1747.93 658.86,1748 v1(720.78,1748)
  Bottom Layer w50: D2_1.2@634.44,1751.06 637.51,1748 v1(720.78,1748)
A12: C1_8.1 J1_8.1 K1_8.4 R0_8.2 R1_8.2 U1_8.1 U1_8.2 U1_8.3 U1_8.4 U3.33 | length 2131.5
  Top Layer w10: U3.33@2582.13,1320.56 2641.99,1320.56 2936.44,1615 3487.28,1615 3568.78,1696.5 3568.78,2001.49 3529.66,2040.61 R0_8.2@3529.66,2041.59
  Top Layer w20: R0_8.2@3514.11,2057.14 R0_8.2@3529.66,2041.59
  Top Layer w40: J1_8.1@3419.2,2260.7 3414.24,2255.75 3414.24,2110.14 K1_8.4@3461.7,2062.68 ; K1_8.4@3460.41,2061.39 3460.41,2060.76 3464.03,2057.14 R0_8.2@3514.11,2057.14
  Bottom Layer w30: U1_8.1@3420.28,2114.16 3420.28,2259.62 J1_8.1@3419.2,2260.7 3419.79,2261.3 3419.79,2351.89 C1_8.1@3420.38,2352.48 3427.03,2359.13 3468.36,2359.13 3496.15,2386.93 R1_8.2@3496.15,2387.91
A13: D2_8.2 F1_8.2 R4_8.1 U3.34 | length 1434.6
  Top Layer w10: U3.34@2582.13,1340.24 2640.47,1340.24 2930.22,1630 3477.04,1630 3520.57,1673.53 v1(3520.57,1748)
  Top Layer w30: F1_8.2@3325.4,1745.96 3326.38,1746.95 3457.6,1746.95 R4_8.1@3458.58,1747.93
  Top Layer w50: R4_8.1@3458.58,1747.93 3458.65,1748 v1(3520.57,1748)
  Bottom Layer w50: D2_8.2@3434.22,1751.05 3437.29,1748 v1(3520.57,1748)
A14: C1_7.1 J1_7.1 K1_7.4 R0_7.2 R1_7.2 U1_7.1 U1_7.2 U1_7.3 U1_7.4 U3.35 | length 1690.5
  Top Layer w10: U3.35@2582.13,1359.93 2614.21,1359.93 2916.75,1662.47 3092.75,1662.47 3168.66,1738.38 3168.66,2001.74 R0_7.2@3129.79,2040.61
  Top Layer w20: R0_7.2@3114.25,2057.14 R0_7.2@3129.79,2041.59 R0_7.2@3129.79,2040.61
  Top Layer w40: J1_7.1@3019.34,2260.7 3014.38,2255.75 3014.38,2110.14 K1_7.4@3061.84,2062.68 ; K1_7.4@3060.55,2061.39 3060.55,2060.76 3064.17,2057.14 R0_7.2@3114.25,2057.14
  Bottom Layer w30: U1_7.1@3020.42,2114.16 3020.42,2259.62 J1_7.1@3019.34,2260.7 3019.93,2261.3 3019.93,2351.89 C1_7.1@3020.52,2352.48 3027.17,2359.13 3068.5,2359.13 3096.29,2386.93 R1_7.2@3096.29,2387.91
A15: D2_7.2 F1_7.2 R4_7.1 U3.36 | length 1000.7
  Top Layer w10: U3.36@2576.22,1379.61 2576.39,1379.61 2588.55,1391.77 2624.84,1391.77 2913.07,1680 3086.92,1680 3120.71,1713.79 v1(3120.71,1748)
  Top Layer w30: F1_7.2@2925.53,1745.96 2926.52,1746.95 3057.74,1746.95 R4_7.1@3058.72,1747.93
  Top Layer w50: R4_7.1@3058.72,1747.93 3058.79,1748 v1(3120.71,1748)
  Bottom Layer w50: D2_7.2@3034.36,1751.05 3037.43,1748 v1(3120.71,1748)
AVDD: C8.1 C22.1 L5.1 U3.30 U3.31 U7.1 U7.2 | length 1666.4
  Top Layer w10: C8.1@2641.99,1273.08 2642.97,1273.08 2674.52,1241.54 2674.52,1076.94 v1(2661.29,1063.72)
  Top Layer w20: L5.1@1593.68,1203.87 1594.03,1203.52 1640.34,1203.52 v1(1640.69,1203.18)
  Top Layer w30: 2585.87,1271.69 C8.1@2641.99,1271.69
  Bottom Layer w15: C22.1@1729.62,1293.28 1729.62,1292.29 1640.69,1203.36 v1(1640.69,1203.18) 1821.72,1022.14 2134.57,1022.14 2161.52,1049.1 2518.84,1049.1 2532.81,1063.07 2660.64,1063.07 v1(2661.29,1063.72)
  Bottom Layer w30: C22.1@1729.62,1293.28 C22.1@1733.76,1297.42
  Bottom Layer w40: C22.1@1733.76,1297.42 1822.29,1297.42
C\S\_ADC: J7.1 R19.2 U5.3 | length 942.9
  Top Layer w10: J7.1@1726.7,493.2 1847.66,372.24 2219.22,372.24 R19.2@2232.92,358.53 ; J7.1@1727.95,493.2 1727.95,604.39 1788.44,664.87 1788.44,725.9 1856.09,793.55 1856.09,794.74 1858.96,797.62 U5.3@1858.96,819.84
C\S\_forwarding: J6.5 R26.1 R56.2 U3.23 | length 1113.6
  Top Layer w10: J6.5@2075.9,1066.05 2083.35,1066.05 2116.17,1033.23 2671.98,1033.23 2727.79,1089.03 v1(2727.79,1133.06) ; R56.2@2494.26,1127.28 2497.48,1130.51 U3.23@2497.48,1196.54
  Bottom Layer w10: v1(2495.27,1159.13) 2566.71,1159.13 2580.65,1173.08 2687.77,1173.08 v1(2727.79,1133.06) 2751.98,1108.87 2752.96,1108.87 2766.66,1095.17 R26.1@2766.66,1094.18
CAPA: C3.1 U3.29 | length 80.1
  Top Layer w10: U3.29@2582.13,1241.82 2616.24,1241.82 2643.43,1214.63 C3.1@2643.43,1207.13
CAPD: C4.1 U3.26 | length 96.9
  Top Layer w8: U3.26@2556.54,1196.54 2557.46,1195.62 2557.46,1184.32 2595.62,1146.16 2595.62,1131.82 2601.62,1125.82 C4.1@2609.12,1125.82
DRDY: R23.1 U4.7 | length 191.2
  Top Layer w10: R23.1@2170.88,578.61 2173.5,575.99 U4.7@2361.01,575.99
